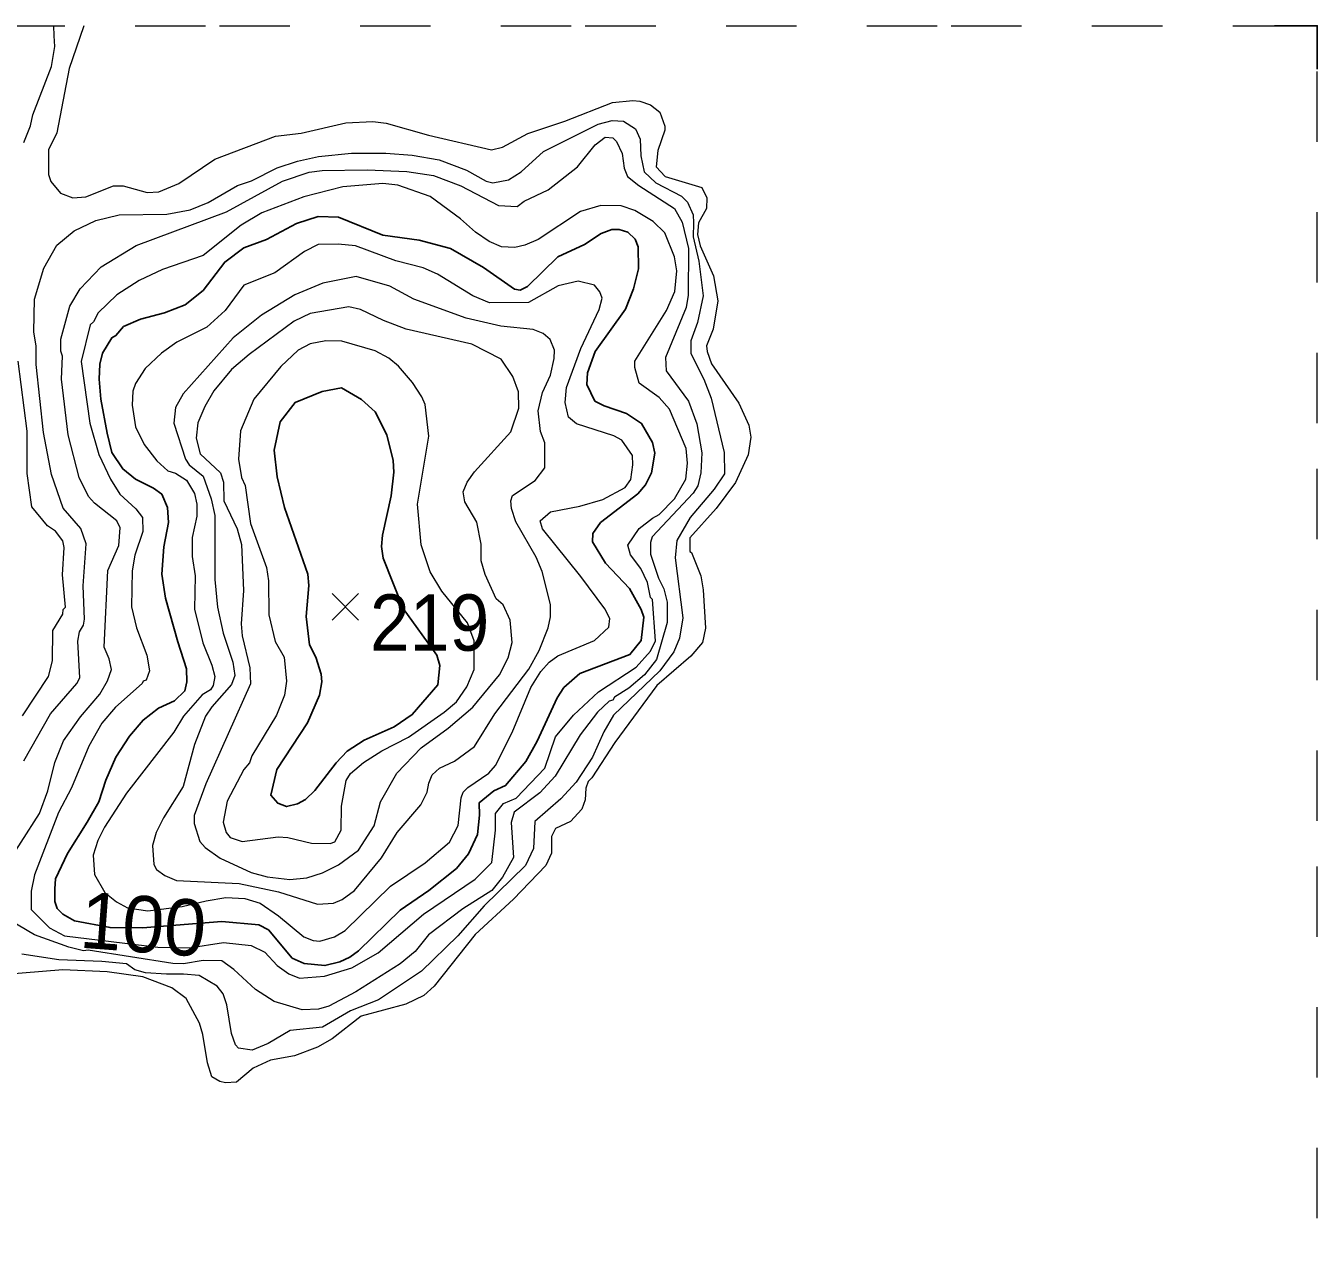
# Model space of a CAD drawing. Extents: x 474.5 to 500, y 7345.7 to 7373.4.
# Drawn here: x 498.165 to 500, y 7371.685 to 7373.417 of the extents above; entities that cross this region are included whole.
import ezdxf
from ezdxf.enums import TextEntityAlignment as Align

# ---------------------------------------------------------------- set-up
doc = ezdxf.new("R2010")
doc.units = 0
doc.header["$LTSCALE"] = 0.032
doc.linetypes.add('SHORT_DASHED', pattern=[2.7, 1.5, -1.2])
for name, color, linetype, lineweight in [('1', 7, 'Continuous', 25), ('2', 7, 'Continuous', 13), ('21', 7, 'Continuous', 25), ('22', 7, 'SHORT_DASHED', 13), ('63', 7, 'Continuous', 25)]:
    doc.layers.add(name, color=color, linetype=linetype, lineweight=lineweight)
doc.layers.add('61', color=7, linetype='Continuous')

msp = doc.modelspace()

# ---------------------------------------------------------------- linework, layer by layer
at = {"layer": '1'}
for points in [[(498.2737, 7372.9514), (498.2869, 7372.9734), (498.2929, 7372.9766), (498.3038, 7372.9896), (498.3278, 7372.9998), (498.3622, 7373.0087), (498.3915, 7373.02), (498.4169, 7373.0408), (498.4476, 7373.0809), (498.4746, 7373.1012), (498.507, 7373.1131), (498.5496, 7373.136), (498.5802, 7373.1456), (498.6094, 7373.1447), (498.6724, 7373.1194), (498.7238, 7373.1123), (498.7686, 7373.1001), (498.8152, 7373.0732), (498.8595, 7373.0423), (498.8672, 7373.0412), (498.8779, 7373.0464), (498.9208, 7373.0882), (498.9587, 7373.1059), (498.9824, 7373.1218), (498.9976, 7373.1272), (499.0082, 7373.1273), (499.0206, 7373.1236), (499.0309, 7373.1134), (499.0349, 7373.1028), (499.0356, 7373.0715), (499.0285, 7373.043), (499.0172, 7373.014), (498.974, 7372.954), (498.9632, 7372.9235), (498.9623, 7372.9072), (498.9735, 7372.8834), (498.9867, 7372.8766), (499.0186, 7372.8657), (499.04, 7372.8516), (499.0554, 7372.8245), (499.0587, 7372.8095), (499.054, 7372.7814), (499.0455, 7372.7646), (499.0346, 7372.7515), (498.9816, 7372.7111), (498.9708, 7372.6951), (498.9704, 7372.6836), (498.9887, 7372.6532), (499.023, 7372.6173), (499.0395, 7372.5875), (499.0429, 7372.5766), (499.0395, 7372.5431), (499.0233, 7372.5233), (498.9521, 7372.4965), (498.9295, 7372.4764), (498.9198, 7372.4618), (498.8915, 7372.4004), (498.8754, 7372.3713), (498.8467, 7372.337), (498.8299, 7372.3295), (498.8092, 7372.3126), (498.8098, 7372.2948), (498.8067, 7372.2676), (498.7938, 7372.24), (498.7769, 7372.2193), (498.7378, 7372.1882), (498.6968, 7372.16), (498.6378, 7372.1024), (498.6253, 7372.0933), (498.6113, 7372.0868), (498.59, 7372.0813), (498.5604, 7372.084), (498.5435, 7372.0918), (498.5096, 7372.1321), (498.496, 7372.139), (498.4433, 7372.1437), (498.3307, 7372.135), (498.2846, 7372.1353), (498.2341, 7372.1448), (498.2173, 7372.1543), (498.2093, 7372.1623), (498.2059, 7372.1723), (498.2059, 7372.1904), (498.2072, 7372.2044), (498.224, 7372.2405), (498.2521, 7372.2853), (498.2688, 7372.3141), (498.2788, 7372.3448), (498.2929, 7372.3776), (498.3121, 7372.4074), (498.3315, 7372.4302), (498.3536, 7372.4469), (498.3763, 7372.4576), (498.391, 7372.4716), (498.3937, 7372.4843), (498.393, 7372.503), (498.381, 7372.5411), (498.3636, 7372.6033), (498.3582, 7372.6374), (498.3609, 7372.6762), (498.3676, 7372.7109)], [(498.3676, 7372.7109), (498.3662, 7372.7323), (498.3582, 7372.751), (498.3462, 7372.7597), (498.3208, 7372.7724), (498.3027, 7372.7871), (498.2873, 7372.8105), (498.2806, 7372.8379), (498.2713, 7372.8864), (498.2693, 7372.9145), (498.27, 7372.9359), (498.2737, 7372.9514)]]:
    msp.add_lwpolyline(points, dxfattribs=at)
msp.add_lwpolyline([(498.5325, 7372.7322), (498.5219, 7372.7756), (498.5179, 7372.8137), (498.5264, 7372.8539), (498.5475, 7372.8816), (498.5858, 7372.8973), (498.6136, 7372.9022), (498.6421, 7372.8858), (498.6614, 7372.868), (498.6781, 7372.8356), (498.6871, 7372.7989), (498.6878, 7372.7824), (498.684, 7372.7489), (498.6716, 7372.6927), (498.6703, 7372.6767), (498.6726, 7372.6601), (498.7009, 7372.5888), (498.749, 7372.5226), (498.7533, 7372.5079), (498.7505, 7372.48), (498.7141, 7372.438), (498.6884, 7372.4204), (498.6458, 7372.4015), (498.6217, 7372.3861), (498.6058, 7372.3696), (498.5758, 7372.3301), (498.5623, 7372.3173), (498.551, 7372.3111), (498.5355, 7372.3072), (498.5229, 7372.312), (498.5132, 7372.3233), (498.5216, 7372.3598), (498.5651, 7372.4264), (498.582, 7372.4655), (498.5856, 7372.4846), (498.5847, 7372.4952), (498.5768, 7372.5197), (498.5681, 7372.5373), (498.5635, 7372.5775), (498.5673, 7372.6212), (498.5657, 7372.6375)], close=True, dxfattribs=at)
at = {"layer": '2'}
msp.add_line((498.2198, 7372.1237), (498.3524, 7372.1076), dxfattribs=at)
for points in [[(498.2472, 7373.4166), (498.2415, 7373.3999), (498.2265, 7373.3562), (498.2091, 7373.2646), (498.1972, 7373.2406), (498.1972, 7373.2056), (498.2006, 7373.1954), (498.214, 7373.1791), (498.2316, 7373.1721), (498.2501, 7373.1737), (498.2895, 7373.1895), (498.303, 7373.1895), (498.3371, 7373.18), (498.3538, 7373.1808), (498.3825, 7373.1925), (498.4336, 7373.2271), (498.5197, 7373.2598), (498.556, 7373.2644), (498.6198, 7373.2789), (498.6579, 7373.2806), (498.6772, 7373.2782), (498.737, 7373.2615), (498.8267, 7373.2407), (498.8425, 7373.2442), (498.8781, 7373.2638), (498.9309, 7373.2812), (498.9987, 7373.3078), (499.0274, 7373.3108), (499.0375, 7373.3098), (499.0525, 7373.3043), (499.0658, 7373.294), (499.0731, 7373.2741), (499.0731, 7373.2686), (499.0632, 7373.2393), (499.0607, 7373.2163), (499.0735, 7373.2026), (499.1257, 7373.187), (499.1328, 7373.1723), (499.1321, 7373.1571), (499.1209, 7373.1367), (499.1194, 7373.1204), (499.1232, 7373.104), (499.1419, 7373.0614), (499.1481, 7373.0258), (499.1418, 7372.9856), (499.1323, 7372.9619), (499.1329, 7372.9537), (499.1393, 7372.9362), (499.1783, 7372.8803), (499.1924, 7372.849), (499.1951, 7372.8321), (499.1912, 7372.8069), (499.1733, 7372.7678), (499.1457, 7372.7308), (499.1083, 7372.6893), (499.1083, 7372.6697), (499.1108, 7372.6681), (499.1239, 7372.6349), (499.1273, 7372.6151), (499.1306, 7372.5609), (499.1265, 7372.5405), (499.1099, 7372.5211), (499.0618, 7372.4793), (499.0019, 7372.3982), (498.9692, 7372.3479), (498.9638, 7372.3429), (498.9607, 7372.3335), (498.9598, 7372.3169), (498.9551, 7372.3035), (498.939, 7372.2858), (498.9178, 7372.2763), (498.912, 7372.2645), (498.9118, 7372.2409), (498.9037, 7372.2233), (498.8577, 7372.1755), (498.8034, 7372.1253), (498.7452, 7372.0519), (498.7304, 7372.0389), (498.7048, 7372.0265), (498.6416, 7372.0092), (498.6004, 7371.9774), (498.5794, 7371.9654), (498.5469, 7371.9531), (498.5128, 7371.9467), (498.4881, 7371.9354), (498.4644, 7371.9157), (498.4488, 7371.9148), (498.4405, 7371.9167), (498.4294, 7371.9232), (498.423, 7371.9432), (498.4166, 7371.9831), (498.4116, 7371.9996), (498.3926, 7372.0344), (498.3725, 7372.0497), (498.3313, 7372.0654), (498.2806, 7372.0725), (498.2175, 7372.0751), (498.1307, 7372.068)], [(498.1622, 7373.2507), (498.1717, 7373.2744), (498.1749, 7373.2903), (498.2012, 7373.359), (498.2059, 7373.3872), (498.2052, 7373.4026), (498.2046, 7373.4166)], [(498.2091, 7373.1049), (498.2335, 7373.1252), (498.2645, 7373.1402), (498.2975, 7373.148), (498.3653, 7373.1492), (498.3985, 7373.1553), (498.4238, 7373.1656), (498.4658, 7373.1898), (498.4858, 7373.1966), (498.5221, 7373.2148), (498.5512, 7373.2246), (498.5807, 7373.2311), (498.6277, 7373.2358), (498.6764, 7373.2358), (498.7139, 7373.2327), (498.7522, 7373.2263), (498.791, 7373.2118), (498.8192, 7373.1961), (498.8286, 7373.1936), (498.8506, 7373.198), (498.8687, 7373.2094), (498.9006, 7373.2381), (498.9784, 7373.2771), (498.9979, 7373.2821), (499.0142, 7373.2812), (499.0315, 7373.2701), (499.038, 7373.2555), (499.0387, 7373.232), (499.0436, 7373.209), (499.0604, 7373.1938), (499.0968, 7373.1746), (499.1054, 7373.1661), (499.1134, 7373.1482), (499.1136, 7373.1368), (499.1133, 7373.117), (499.1213, 7373.0821), (499.1273, 7373.033), (499.1194, 7372.9952), (499.1099, 7372.9693), (499.1099, 7372.9511), (499.1282, 7372.9148), (499.1387, 7372.8874), (499.1575, 7372.8105), (499.1577, 7372.7802), (499.1429, 7372.7582), (499.1092, 7372.7182), (499.0898, 7372.6851), (499.0875, 7372.6605), (499.0986, 7372.5754), (499.0938, 7372.5466), (499.0857, 7372.5272), (499.0657, 7372.5001), (499.0001, 7372.4369), (498.9865, 7372.4134), (498.9701, 7372.3772), (498.9469, 7372.3421), (498.9253, 7372.3182), (498.8883, 7372.2859), (498.8864, 7372.2477), (498.875, 7372.2234), (498.816, 7372.1662), (498.7787, 7372.1236), (498.7272, 7372.0731), (498.666, 7372.0327), (498.6263, 7372.0168), (498.5864, 7371.9938), (498.5405, 7371.989), (498.5091, 7371.9706), (498.4864, 7371.9612), (498.4673, 7371.9641), (498.4627, 7371.9685), (498.4573, 7371.9847), (498.4507, 7372.0254), (498.4451, 7372.041), (498.4367, 7372.0518), (498.4112, 7372.067), (498.389, 7372.0692), (498.3647, 7372.0692), (498.335, 7372.071), (498.32, 7372.0751), (498.3082, 7372.0836), (498.2727, 7372.0869), (498.2118, 7372.0894), (498.1593, 7372.0974)], [(498.9741, 7373.2477), (498.9882, 7373.2586), (498.9989, 7373.2573), (499.0045, 7373.2523), (499.0123, 7373.2353), (499.0154, 7373.2145), (499.0201, 7373.2027), (499.0359, 7373.1899), (499.0865, 7373.1569), (499.0974, 7373.1376), (499.1066, 7373.1002), (499.1059, 7373.0338), (499.1031, 7373.0164), (499.074, 7372.9454), (499.0749, 7372.9264), (499.1065, 7372.8835), (499.1186, 7372.8511), (499.1257, 7372.8101), (499.1242, 7372.7814), (499.1197, 7372.7629), (499.1132, 7372.7527), (499.0551, 7372.6906), (499.0525, 7372.6827), (499.0525, 7372.6658), (499.0641, 7372.6316), (499.0716, 7372.6167), (499.0763, 7372.5976), (499.0763, 7372.569), (499.061, 7372.5162), (499.0443, 7372.4946), (499.0219, 7372.4756), (499.0015, 7372.4625), (498.999, 7372.4583), (498.994, 7372.457), (498.9774, 7372.4412), (498.9526, 7372.4093), (498.917, 7372.3503), (498.8955, 7372.3267), (498.8589, 7372.2995), (498.8545, 7372.2846), (498.8577, 7372.2349), (498.8423, 7372.207), (498.8272, 7372.1881), (498.7857, 7372.1619), (498.7372, 7372.1252), (498.718, 7372.1013), (498.6969, 7372.0837), (498.6341, 7372.0438), (498.5955, 7372.0238), (498.581, 7372.0192), (498.5575, 7372.0185), (498.518, 7372.0303), (498.4913, 7372.0473), (498.4607, 7372.0758), (498.4434, 7372.0878), (498.4168, 7372.0886), (498.3892, 7372.0839), (498.3737, 7372.0842), (498.2537, 7372.1033), (498.247, 7372.1024), (498.2258, 7372.1074), (498.177, 7372.1251), (498.131, 7372.1524)], [(498.783, 7373.1894), (498.8364, 7373.1613), (498.8631, 7373.1601), (498.8733, 7373.1675), (498.9072, 7373.1836), (498.949, 7373.2164), (498.9741, 7373.2477)], [(498.1324, 7372.2161), (498.1844, 7372.2976), (498.1964, 7372.3298), (498.206, 7372.3697), (498.2185, 7372.4008), (498.2428, 7372.4346), (498.2702, 7372.4671), (498.2809, 7372.4859), (498.2865, 7372.5019), (498.2835, 7372.5173), (498.2762, 7372.5339), (498.2816, 7372.6427), (498.2971, 7372.678), (498.2992, 7372.7034), (498.2942, 7372.7134), (498.2623, 7372.7385), (498.2542, 7372.7479), (498.2407, 7372.775), (498.2251, 7372.8356), (498.2156, 7372.9146), (498.217, 7372.9472), (498.2148, 7372.9546), (498.2148, 7372.9715), (498.2273, 7373.0183), (498.242, 7373.0429), (498.272, 7373.0743), (498.3216, 7373.1046), (498.4503, 7373.1526), (498.5296, 7373.1958), (498.5676, 7373.2088), (498.586, 7373.2111), (498.65, 7373.212), (498.7064, 7373.2095), (498.7442, 7373.204), (498.783, 7373.1894)], [(498.3524, 7372.1076), (498.3969, 7372.1067), (498.4457, 7372.1141), (498.4849, 7372.11), (498.5045, 7372.1004), (498.5222, 7372.0813), (498.5386, 7372.0696), (498.5539, 7372.0634), (498.5893, 7372.0663), (498.6282, 7372.0781), (498.6654, 7372.0992), (498.7298, 7372.1544), (498.8034, 7372.2043), (498.8271, 7372.2279), (498.8322, 7372.2735), (498.8324, 7372.2976), (498.8439, 7372.3116), (498.8619, 7372.3194), (498.9024, 7372.3617), (498.9176, 7372.4061), (498.943, 7372.4372), (498.9789, 7372.4702), (499.0321, 7372.5055), (499.0527, 7372.5282), (499.0595, 7372.5429), (499.0554, 7372.6015), (499.0528, 7372.6044), (499.0485, 7372.6258), (499.0388, 7372.6455), (499.0243, 7372.6649), (499.0205, 7372.6788), (499.0366, 7372.7022), (499.0555, 7372.7173), (499.0651, 7372.7221), (499.0869, 7372.7444), (499.103, 7372.7726), (499.1054, 7372.7952), (499.1034, 7372.8162), (499.0797, 7372.8718), (499.0648, 7372.8884), (499.0364, 7372.909), (499.0302, 7372.931), (499.0303, 7372.9401), (499.0754, 7373.0122), (499.0874, 7373.0391), (499.0898, 7373.0683), (499.0866, 7373.0884), (499.0731, 7373.1225), (499.0563, 7373.1386), (499.0303, 7373.1543), (499.0107, 7373.1609), (498.9821, 7373.1616), (498.9532, 7373.1527), (498.8931, 7373.1131), (498.8741, 7373.1049), (498.8599, 7373.1019), (498.841, 7373.1025), (498.8232, 7373.1102), (498.8037, 7373.1237), (498.7826, 7373.1425), (498.7394, 7373.1741), (498.6937, 7373.1903), (498.6721, 7373.1927), (498.6153, 7373.1879), (498.5599, 7373.1738), (498.5001, 7373.1511), (498.4711, 7373.1334), (498.4171, 7373.0905), (498.3593, 7373.0705), (498.3262, 7373.0546), (498.2943, 7373.0346), (498.2677, 7373.0089), (498.261, 7372.9959), (498.2564, 7372.9917), (498.2435, 7372.9396), (498.256, 7372.8523), (498.2686, 7372.8076), (498.2852, 7372.7726), (498.2987, 7372.7514), (498.3212, 7372.7305), (498.3305, 7372.7182), (498.3312, 7372.6982), (498.32, 7372.6643), (498.316, 7372.642), (498.3153, 7372.5913), (498.3221, 7372.561), (498.3368, 7372.5226), (498.3406, 7372.5002), (498.3359, 7372.4868), (498.3315, 7372.4852), (498.3304, 7372.482), (498.2921, 7372.4484), (498.2728, 7372.4259), (498.2544, 7372.3929), (498.2296, 7372.3337), (498.2114, 7372.299), (498.1773, 7372.2102), (498.1724, 7372.1872), (498.1726, 7372.1611), (498.1985, 7372.1351), (498.2198, 7372.1237)], [(498.2467, 7372.5652), (498.2482, 7372.5735), (498.2466, 7372.6209), (498.2506, 7372.6806), (498.2432, 7372.7023), (498.2181, 7372.7314), (498.2013, 7372.7791), (498.19, 7372.8388), (498.1798, 7372.9354), (498.1796, 7372.9617), (498.1765, 7372.982), (498.1772, 7373.0281), (498.1905, 7373.0721), (498.2091, 7373.1049)], [(498.9798, 7373.0137), (498.9838, 7373.0297), (498.9806, 7373.0387), (498.9728, 7373.0481), (498.9497, 7373.0539), (498.9213, 7373.0474), (498.879, 7373.0236), (498.824, 7373.0229), (498.8003, 7373.0332), (498.7498, 7373.0637), (498.7295, 7373.0727), (498.6905, 7373.0828), (498.6333, 7373.1041), (498.6088, 7373.1065), (498.5804, 7373.1058), (498.5607, 7373.0961), (498.5187, 7373.0656), (498.4749, 7373.0483), (498.4483, 7373.0124), (498.4223, 7372.9887), (498.3793, 7372.9671), (498.3579, 7372.9515), (498.3346, 7372.9296), (498.3208, 7372.9086), (498.3168, 7372.8974), (498.3161, 7372.8775), (498.3208, 7372.8468), (498.3333, 7372.8218), (498.3513, 7372.7984), (498.3669, 7372.7845), (498.3774, 7372.7811), (498.3932, 7372.7709), (498.4048, 7372.7519), (498.4077, 7372.737), (498.4077, 7372.7199), (498.4015, 7372.6894), (498.4015, 7372.6628), (498.4054, 7372.6349), (498.4047, 7372.5878), (498.4166, 7372.54), (498.4294, 7372.508), (498.4333, 7372.4921), (498.4311, 7372.4794), (498.4275, 7372.4731), (498.4157, 7372.466), (498.3888, 7372.4359), (498.3753, 7372.413), (498.3082, 7372.3263), (498.2766, 7372.278), (498.2672, 7372.2591), (498.2606, 7372.2382), (498.2624, 7372.2108), (498.2771, 7372.1852), (498.2937, 7372.1717), (498.3095, 7372.1631), (498.3384, 7372.1592), (498.387, 7372.1651), (498.4211, 7372.1733), (498.4492, 7372.178), (498.4759, 7372.1765), (498.4979, 7372.17), (498.5238, 7372.152), (498.5599, 7372.1223), (498.573, 7372.1171), (498.5828, 7372.1162), (498.6035, 7372.1219), (498.6186, 7372.1311), (498.6831, 7372.1941), (498.7324, 7372.2272), (498.7672, 7372.2566), (498.7795, 7372.2802), (498.7835, 7372.3198), (498.7865, 7372.3275), (498.7932, 7372.3344), (498.823, 7372.3548), (498.8324, 7372.3657), (498.8561, 7372.4125), (498.8826, 7372.4766), (498.8967, 7372.4991), (498.9085, 7372.5123), (498.9209, 7372.5212), (498.9729, 7372.543), (498.9933, 7372.562), (498.9949, 7372.5743), (498.9877, 7372.588), (498.9534, 7372.6343), (498.899, 7372.702), (498.8956, 7372.7135), (498.9103, 7372.7263), (498.9521, 7372.7341), (498.9851, 7372.7435), (499.0164, 7372.7605), (499.0245, 7372.7718), (499.0275, 7372.7929), (499.0268, 7372.8063), (499.0117, 7372.8281), (499.0007, 7372.8342), (498.9473, 7372.8512), (498.9359, 7372.8606), (498.9312, 7372.8814), (498.9333, 7372.9029)], [(498.9333, 7372.9029), (498.9536, 7372.9582), (498.9798, 7373.0137)], [(498.1603, 7372.4362), (498.197, 7372.4921), (498.2027, 7372.5144), (498.2035, 7372.5575), (498.2177, 7372.5808), (498.2181, 7372.5872), (498.2211, 7372.5907), (498.2172, 7372.6366), (498.2195, 7372.6756), (498.2173, 7372.6848), (498.2069, 7372.6986), (498.1956, 7372.706), (498.1733, 7372.7334), (498.167, 7372.7807), (498.1668, 7372.8407), (498.1542, 7372.9404)], [(498.1619, 7372.3724), (498.2, 7372.4391), (498.2373, 7372.4819), (498.2417, 7372.49), (498.2387, 7372.5421), (498.2412, 7372.5557), (498.2467, 7372.5652)]]:
    msp.add_lwpolyline(points, dxfattribs=at)
for points in [[(498.8614, 7372.7117), (498.855, 7372.731), (498.8541, 7372.7418), (498.8564, 7372.7494), (498.8887, 7372.7704), (498.9024, 7372.7886), (498.9024, 7372.8242), (498.8961, 7372.8404), (498.8929, 7372.8696), (498.8992, 7372.8958), (498.9104, 7372.9202), (498.9159, 7372.9438), (498.916, 7372.9559), (498.9099, 7372.9711), (498.9001, 7372.9797), (498.8859, 7372.9854), (498.84, 7372.9898), (498.7905, 7373.0014), (498.7162, 7373.0282), (498.682, 7373.0468), (498.6343, 7373.0603), (498.5868, 7373.0508), (498.5471, 7373.0343), (498.4999, 7373.0057), (498.4595, 7372.9732), (498.3883, 7372.8939), (498.3775, 7372.8741), (498.375, 7372.8523), (498.3916, 7372.8007), (498.3971, 7372.7927), (498.4171, 7372.7767), (498.4285, 7372.7447), (498.4333, 7372.7207), (498.4333, 7372.6301), (498.4372, 7372.5906), (498.4454, 7372.5535), (498.459, 7372.5125), (498.4619, 7372.4937), (498.4573, 7372.4806), (498.429, 7372.4491), (498.4202, 7372.4358), (498.4047, 7372.3953), (498.3885, 7372.3357), (498.3607, 7372.2912), (498.3502, 7372.2703), (498.3448, 7372.2517), (498.3469, 7372.2251), (498.3504, 7372.218), (498.3623, 7372.2092), (498.3788, 7372.202), (498.4682, 7372.198), (498.524, 7372.186), (498.5796, 7372.1685), (498.6021, 7372.1702), (498.6145, 7372.1753), (498.6319, 7372.1879), (498.6702, 7372.2346), (498.6927, 7372.2702), (498.7261, 7372.3097), (498.7354, 7372.3275), (498.7374, 7372.3404), (498.7422, 7372.3521), (498.7529, 7372.362), (498.7743, 7372.3718), (498.8026, 7372.3926), (498.8312, 7372.4388), (498.8799, 7372.5025), (498.8944, 7372.529), (498.9071, 7372.561), (498.9103, 7372.5769), (498.9103, 7372.5944), (498.8988, 7372.6414), (498.8903, 7372.6617)], [(498.8178, 7372.637), (498.8122, 7372.6565), (498.8121, 7372.6802), (498.8057, 7372.7112), (498.7888, 7372.7404), (498.7863, 7372.7545), (498.7922, 7372.7681), (498.8026, 7372.7827), (498.8541, 7372.8396), (498.8657, 7372.8734), (498.8648, 7372.8966), (498.8568, 7372.9186), (498.8402, 7372.9428), (498.7989, 7372.9643), (498.7055, 7372.9855), (498.6732, 7372.9979), (498.6405, 7373.0138), (498.6237, 7373.0172), (498.5692, 7373.0077), (498.5464, 7372.9972), (498.4824, 7372.9498), (498.4574, 7372.9281), (498.4321, 7372.8981), (498.4192, 7372.8758), (498.4093, 7372.8527), (498.407, 7372.8308), (498.4126, 7372.8083), (498.4415, 7372.7814), (498.446, 7372.7683), (498.4462, 7372.7419), (498.465, 7372.7019), (498.4715, 7372.6796), (498.4741, 7372.6142), (498.471, 7372.5669), (498.4724, 7372.55), (498.4831, 7372.5042), (498.4844, 7372.4818), (498.4208, 7372.3397), (498.4039, 7372.2944), (498.4039, 7372.2831), (498.4122, 7372.2576), (498.4196, 7372.2491), (498.4413, 7372.2338), (498.4853, 7372.2134), (498.5078, 7372.2076), (498.5401, 7372.2036), (498.5644, 7372.206), (498.5863, 7372.213), (498.6091, 7372.2244), (498.6375, 7372.2451), (498.6597, 7372.2799), (498.6689, 7372.3142), (498.6921, 7372.3548), (498.7267, 7372.3908), (498.7652, 7372.4188), (498.8002, 7372.4483), (498.8378, 7372.4945), (498.8505, 7372.5187), (498.8561, 7372.5403), (498.853, 7372.5719), (498.8432, 7372.5937), (498.8331, 7372.6026)], [(498.7375, 7372.8336), (498.7324, 7372.8784), (498.7277, 7372.8897), (498.7145, 7372.9097), (498.6946, 7372.933), (498.6809, 7372.9442), (498.6612, 7372.9548), (498.6139, 7372.9685), (498.591, 7372.9693), (498.569, 7372.9646), (498.552, 7372.9556), (498.5273, 7372.9326), (498.489, 7372.8862), (498.47, 7372.8414), (498.4669, 7372.8011), (498.4716, 7372.775), (498.4764, 7372.7635), (498.4843, 7372.7093), (498.5067, 7372.6471), (498.5099, 7372.6279), (498.51, 7372.5795), (498.5194, 7372.5418), (498.5322, 7372.5194), (498.5354, 7372.4853), (498.5323, 7372.4655), (498.5213, 7372.437), (498.4861, 7372.3793), (498.4827, 7372.3695), (498.4747, 7372.3597), (498.4508, 7372.315), (498.4453, 7372.2853), (498.4494, 7372.2703), (498.4552, 7372.2631), (498.4721, 7372.2578), (498.5233, 7372.2642), (498.5373, 7372.2633), (498.5708, 7372.2554), (498.5976, 7372.2547), (498.6038, 7372.257), (498.6128, 7372.2738), (498.6137, 7372.3078), (498.6201, 7372.3445), (498.6263, 7372.3542), (498.6448, 7372.37), (498.6707, 7372.3865), (498.7088, 7372.4058), (498.7596, 7372.4414), (498.7767, 7372.4561), (498.7917, 7372.4774), (498.8018, 7372.502), (498.8018, 7372.5426), (498.7924, 7372.5682), (498.7562, 7372.6133), (498.7397, 7372.6409), (498.7269, 7372.6793), (498.7214, 7372.737)]]:
    msp.add_lwpolyline(points, close=True, dxfattribs=at)
at = {"layer": '21'}
for p, q in [((498.6001, 7372.6098), (498.6376, 7372.5723)), ((498.6376, 7372.6098), (498.6001, 7372.5723))]:
    msp.add_line(p, q, dxfattribs=at)
at = {"layer": '22'}
for points in [[(488.561, 7373.4122), (489.0809, 7373.4126), (489.6009, 7373.413), (490.1208, 7373.4133), (490.6408, 7373.4137), (491.1607, 7373.414), (491.6807, 7373.4143), (492.2006, 7373.4146), (492.7206, 7373.4149), (493.2406, 7373.4151), (493.7605, 7373.4154), (494.2805, 7373.4156), (494.8004, 7373.4158), (495.3204, 7373.416), (495.8403, 7373.4161), (496.3603, 7373.4163), (496.8802, 7373.4164), (497.4002, 7373.4165), (497.9201, 7373.4166), (498.4401, 7373.4166), (498.96, 7373.4167), (499.48, 7373.4167), (500, 7373.4167)], [(500, 7366.0735), (500, 7366.6384), (500, 7367.2032), (500, 7367.7681), (500, 7368.333), (500, 7368.8978), (500, 7369.4627), (500, 7370.0276), (500, 7370.5924), (500, 7371.1573), (500, 7371.7221), (500, 7372.287), (500, 7372.8519), (500, 7373.4167)]]:
    msp.add_lwpolyline(points, dxfattribs=at)
at = {"layer": '63'}
msp.add_lwpolyline([(500, 7373.3551), (500, 7373.4167), (499.9393, 7373.4167)], dxfattribs=at)

# ---------------------------------------------------------------- texts
at = {"layer": '61', "width": 0.95}
msp.add_text('219', height=0.08, dxfattribs=at).set_placement((498.7387, 7372.5287), align=Align.CENTER)
at = {"layer": '61'}
msp.add_text('100', height=0.08, rotation=355.736, dxfattribs=at).set_placement((498.3289, 7372.1002), align=Align.CENTER)

doc.saveas('drawing.dxf')
